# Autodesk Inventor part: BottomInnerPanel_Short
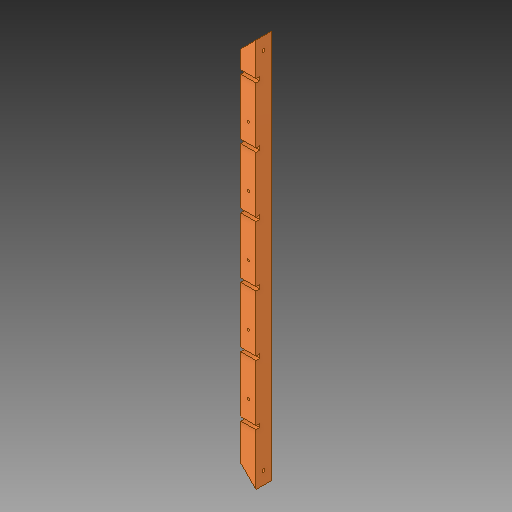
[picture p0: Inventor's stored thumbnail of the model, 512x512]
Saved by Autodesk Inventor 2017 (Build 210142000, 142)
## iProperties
Created: 2017-05
Part Number: BottomInnerPanel_Short
Material: Generic
Document SubType Name: Modeling
Designer: Savy
Density: 1 g/cm^3
Appearance: Default
Author: Savy
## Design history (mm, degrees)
feature "SOLID1"
body "Solid1"
